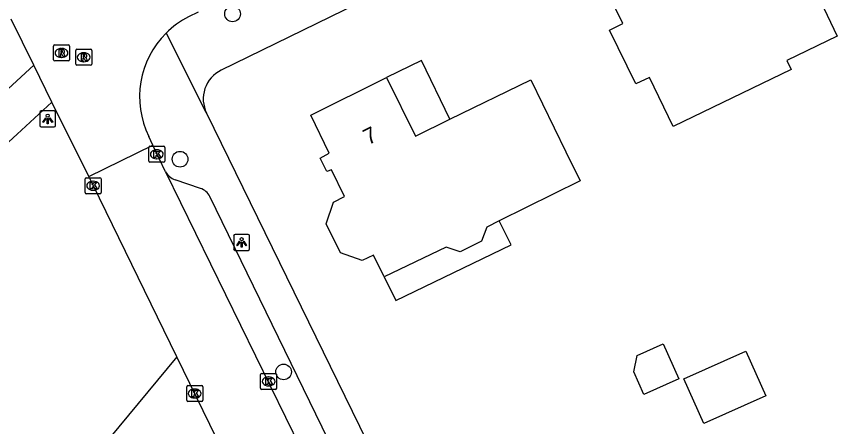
# Model space of a CAD drawing. Extents: x 160457 to 162082, y 388340 to 389736.
# Drawn here: x 160764.7 to 160816.2, y 388623.8 to 388649.4 of the extents above; entities that cross this region are included whole.
import ezdxf

# ---------------------------------------------------------------- set-up
doc = ezdxf.new("R2010")
doc.units = 0
for name, color, linetype in [('IMGEO_Boom', 7, 'Continuous'), ('IMGEO_Groenvoorziening', 7, 'Continuous'), ('IMGEO_Kolk', 7, 'Continuous'), ('IMGEO_Lichtpunt', 7, 'Continuous'), ('IMGEO_Pand', 7, 'Continuous'), ('IMGEO_Pand_nummerreeks', 7, 'Continuous'), ('IMGEO_Pand_overbouw', 7, 'Continuous'), ('IMGEO_Rijbaan_lokaal_open', 7, 'Continuous'), ('IMGEO_Rioolput', 7, 'Continuous'), ('IMGEO_Voetpad_open', 7, 'Continuous')]:
    doc.layers.add(name, color=color, linetype=linetype)

msp = doc.modelspace()

# ---------------------------------------------------------------- linework, layer by layer
at = {"layer": 'IMGEO_Boom'}
for centre in [(160778.162, 388649.577), (160774.883, 388640.505), (160781.349, 388627.22)]:
    msp.add_circle(centre, 0.489, dxfattribs=at)
at = {"layer": 'IMGEO_Groenvoorziening'}
msp.add_lwpolyline([(160774.68, 388628.159), (160767.455, 388619.42)], dxfattribs=at)
at = {"layer": 'IMGEO_Kolk'}
for p, q in [((160773.007, 388641.312), (160773.859, 388641.312)), ((160772.932, 388640.386), (160772.932, 388641.238)), ((160773.42, 388641.092), (160773.445, 388641.092)), ((160773.933, 388641.238), (160773.933, 388640.386)), ((160773.859, 388640.312), (160773.007, 388640.312)), ((160773.443, 388640.532), (160773.418, 388640.532)), ((160768.958, 388638.419), (160768.958, 388639.271)), ((160769.033, 388639.345), (160769.885, 388639.345)), ((160769.959, 388639.271), (160769.959, 388638.419)), ((160769.446, 388639.125), (160769.471, 388639.125)), ((160769.885, 388638.345), (160769.033, 388638.345)), ((160769.469, 388638.565), (160769.444, 388638.565)), ((160779.914, 388626.201), (160779.914, 388627.053)), ((160779.989, 388627.127), (160780.841, 388627.127)), ((160780.402, 388626.907), (160780.427, 388626.907)), ((160780.915, 388627.053), (160780.915, 388626.201)), ((160775.375, 388626.371), (160776.227, 388626.371)), ((160780.425, 388626.347), (160780.4, 388626.347)), ((160775.3, 388625.445), (160775.3, 388626.297)), ((160775.788, 388626.151), (160775.813, 388626.151)), ((160776.301, 388626.297), (160776.301, 388625.445)), ((160780.841, 388626.127), (160779.989, 388626.127)), ((160776.227, 388625.371), (160775.375, 388625.371)), ((160775.811, 388625.591), (160775.786, 388625.591))]:
    msp.add_line(p, q, dxfattribs=at)
for points in [[(160773.007, 388641.312), (160773.859, 388641.312)], [(160772.932, 388640.386), (160772.932, 388641.238)], [(160773.253, 388641.012), (160773.376, 388641.012), (160773.376, 388640.861), (160773.506, 388641.012), (160773.67, 388641.012), (160773.524, 388640.861), (160773.677, 388640.612), (160773.525, 388640.612), (160773.44, 388640.776), (160773.376, 388640.709), (160773.376, 388640.612), (160773.253, 388640.612), (160773.253, 388641.012)], [(160773.933, 388641.238), (160773.933, 388640.386)], [(160773.859, 388640.312), (160773.007, 388640.312)], [(160768.958, 388638.419), (160768.958, 388639.271)], [(160769.033, 388639.345), (160769.885, 388639.345)], [(160769.959, 388639.271), (160769.959, 388638.419)], [(160769.279, 388639.045), (160769.402, 388639.045), (160769.402, 388638.894), (160769.532, 388639.045), (160769.696, 388639.045), (160769.55, 388638.894), (160769.703, 388638.645), (160769.551, 388638.645), (160769.466, 388638.809), (160769.402, 388638.742), (160769.402, 388638.645), (160769.279, 388638.645), (160769.279, 388639.045)], [(160769.885, 388638.345), (160769.033, 388638.345)], [(160779.914, 388626.201), (160779.914, 388627.053)], [(160779.989, 388627.127), (160780.841, 388627.127)], [(160780.235, 388626.827), (160780.358, 388626.827), (160780.358, 388626.676), (160780.488, 388626.827), (160780.652, 388626.827), (160780.506, 388626.676), (160780.659, 388626.427), (160780.507, 388626.427), (160780.422, 388626.591), (160780.358, 388626.524), (160780.358, 388626.427), (160780.235, 388626.427), (160780.235, 388626.827)], [(160780.915, 388627.053), (160780.915, 388626.201)], [(160775.375, 388626.371), (160776.227, 388626.371)], [(160775.3, 388625.445), (160775.3, 388626.297)], [(160775.621, 388626.071), (160775.744, 388626.071), (160775.744, 388625.92), (160775.874, 388626.071), (160776.038, 388626.071), (160775.892, 388625.92), (160776.045, 388625.671), (160775.893, 388625.671), (160775.808, 388625.835), (160775.744, 388625.768), (160775.744, 388625.671), (160775.621, 388625.671), (160775.621, 388626.071)], [(160776.301, 388626.297), (160776.301, 388625.445)], [(160780.841, 388626.127), (160779.989, 388626.127)], [(160776.227, 388625.371), (160775.375, 388625.371)]]:
    msp.add_lwpolyline(points, dxfattribs=at)
for centre, start, end in [((160773.009, 388641.236), 91.552, 178.448), ((160773.009, 388641.236), 91.552, 178.448), ((160773.857, 388641.236), 1.552, 88.448), ((160773.857, 388641.236), 1.552, 88.448), ((160773.009, 388640.388), 181.552, 268.448), ((160773.009, 388640.388), 181.552, 268.448), ((160773.857, 388640.388), 271.552, 358.448), ((160773.857, 388640.388), 271.552, 358.448), ((160769.035, 388639.269), 91.552, 178.448), ((160769.035, 388639.269), 91.552, 178.448), ((160769.883, 388639.269), 1.552, 88.448), ((160769.883, 388639.269), 1.552, 88.448), ((160769.035, 388638.421), 181.552, 268.448), ((160769.035, 388638.421), 181.552, 268.448), ((160769.883, 388638.421), 271.552, 358.448), ((160769.883, 388638.421), 271.552, 358.448), ((160779.991, 388627.051), 91.552, 178.448), ((160779.991, 388627.051), 91.552, 178.448), ((160780.839, 388627.051), 1.552, 88.448), ((160780.839, 388627.051), 1.552, 88.448), ((160775.377, 388626.295), 91.552, 178.448), ((160775.377, 388626.295), 91.552, 178.448), ((160776.225, 388626.295), 1.552, 88.448), ((160776.225, 388626.295), 1.552, 88.448), ((160779.991, 388626.203), 181.552, 268.448), ((160779.991, 388626.203), 181.552, 268.448), ((160780.839, 388626.203), 271.552, 358.448), ((160780.839, 388626.203), 271.552, 358.448), ((160775.377, 388625.447), 181.552, 268.448), ((160775.377, 388625.447), 181.552, 268.448), ((160776.225, 388625.447), 271.552, 358.448), ((160776.225, 388625.447), 271.552, 358.448)]:
    msp.add_arc(centre, 0.0765, start, end, dxfattribs=at)
for centre, major_axis, ratio, start_param, end_param in [((160773.419, 388640.812), (-0.387, 0.002), 0.722429, 4.712389, 7.853982), ((160773.444, 388640.812), (-0.39, 0.002), 0.717154, 1.570796, 4.712389), ((160769.445, 388638.845), (-0.387, 0.002), 0.722429, 4.712389, 7.853982), ((160769.47, 388638.845), (-0.39, 0.002), 0.717154, 1.570796, 4.712389), ((160780.401, 388626.627), (-0.387, 0.002), 0.722429, 4.712389, 7.853982), ((160780.426, 388626.627), (-0.39, 0.002), 0.717154, 1.570796, 4.712389), ((160775.787, 388625.871), (-0.387, 0.002), 0.722429, 4.712389, 7.853982), ((160775.812, 388625.871), (-0.39, 0.002), 0.717154, 1.570796, 4.712389)]:
    msp.add_ellipse(centre, major_axis=major_axis, ratio=ratio, start_param=start_param, end_param=end_param, dxfattribs=at)
at = {"layer": 'IMGEO_Lichtpunt'}
for p, q in [((160766.125, 388643.422), (160766.125, 388642.615)), ((160766.125, 388643.422), (160766.125, 388642.615)), ((160767.027, 388643.517), (160766.219, 388643.517)), ((160767.027, 388643.517), (160766.219, 388643.517)), ((160767.121, 388642.615), (160767.121, 388643.422)), ((160767.121, 388642.615), (160767.121, 388643.422)), ((160766.219, 388642.521), (160767.027, 388642.521)), ((160766.219, 388642.521), (160767.027, 388642.521)), ((160778.232, 388635.713), (160778.232, 388634.906)), ((160778.232, 388635.713), (160778.232, 388634.906)), ((160779.134, 388635.808), (160778.326, 388635.808)), ((160779.134, 388635.808), (160778.326, 388635.808)), ((160779.228, 388634.906), (160779.228, 388635.713)), ((160779.228, 388634.906), (160779.228, 388635.713)), ((160778.326, 388634.812), (160779.134, 388634.812)), ((160778.326, 388634.812), (160779.134, 388634.812))]:
    msp.add_line(p, q, dxfattribs=at)
for points in [[(160766.499, 388643.086), (160766.538, 388643.058), (160766.35, 388642.796), (160766.312, 388642.823), (160766.499, 388643.086)], [(160766.601, 388643.038), (160766.648, 388643.038), (160766.648, 388642.716), (160766.601, 388642.716), (160766.601, 388643.038)], [(160766.711, 388643.058), (160766.749, 388643.085), (160766.936, 388642.823), (160766.897, 388642.795), (160766.711, 388643.058)], [(160778.606, 388635.377), (160778.645, 388635.349), (160778.457, 388635.087), (160778.419, 388635.114), (160778.606, 388635.377)], [(160778.708, 388635.329), (160778.755, 388635.329), (160778.755, 388635.007), (160778.708, 388635.007), (160778.708, 388635.329)], [(160778.818, 388635.349), (160778.856, 388635.376), (160779.043, 388635.114), (160779.004, 388635.086), (160778.818, 388635.349)]]:
    msp.add_lwpolyline(points, dxfattribs=at)
for centre in [(160766.624, 388643.22), (160778.731, 388635.511)]:
    msp.add_circle(centre, 0.0994, dxfattribs=at)
for centre, start, end in [((160766.219, 388643.422), 90, 180), ((160766.219, 388643.422), 90, 180), ((160767.027, 388643.422), 0, 90), ((160767.027, 388643.422), 0, 90), ((160766.219, 388642.615), 180, 270), ((160766.219, 388642.615), 180, 270), ((160767.027, 388642.615), 270, 0), ((160767.027, 388642.615), 270, 360), ((160778.326, 388635.713), 90, 180), ((160778.326, 388635.713), 90, 180), ((160779.134, 388635.713), 0, 90), ((160779.134, 388635.713), 0, 90), ((160778.326, 388634.906), 180, 270), ((160778.326, 388634.906), 180, 270), ((160779.134, 388634.906), 270, 0), ((160779.134, 388634.906), 270, 360)]:
    msp.add_arc(centre, 0.0946, start, end, dxfattribs=at)
at = {"layer": 'IMGEO_Pand'}
for points in [[(160803.322, 388645.208), (160801.68, 388648.558), (160802.525, 388648.971), (160801.014, 388652.061), (160808.386, 388655.648), (160809.939, 388652.456), (160813.089, 388653.988), (160815.272, 388649.49), (160815.901, 388648.194), (160812.757, 388646.669), (160813.028, 388646.113), (160805.662, 388642.539), (160804.175, 388645.61), (160803.322, 388645.208)], [(160787.615, 388633.148), (160786.95, 388634.517), (160786.249, 388634.188), (160784.909, 388634.649), (160784.005, 388636.474), (160784.453, 388637.827), (160785.156, 388638.175), (160784.348, 388639.831), (160784.042, 388639.726), (160783.63, 388640.568), (160784.199, 388640.874), (160783.058, 388643.254), (160787.772, 388645.597), (160789.57, 388641.947), (160791.725, 388642.998), (160796.771, 388645.458), (160798.965, 388640.966), (160799.852, 388639.15), (160794.809, 388636.654), (160794.022, 388636.26), (160793.707, 388635.386), (160792.363, 388634.724), (160791.488, 388635.019), (160787.615, 388633.148)], [(160803.841, 388625.817), (160803.21, 388627.225), (160803.414, 388628.236), (160805.038, 388628.964), (160806.012, 388626.79), (160803.841, 388625.817)], [(160807.583, 388623.992), (160806.33, 388626.789), (160810.19, 388628.514), (160811.443, 388625.718), (160807.583, 388623.992)]]:
    msp.add_lwpolyline(points, dxfattribs=at)
at = {"layer": 'IMGEO_Pand_overbouw'}
for points in [[(160787.772, 388645.597), (160789.57, 388641.947), (160791.725, 388642.998), (160789.952, 388646.666)], [(160794.809, 388636.654), (160794.022, 388636.26), (160793.707, 388635.386), (160792.363, 388634.724), (160791.488, 388635.019), (160787.615, 388633.148), (160788.343, 388631.688), (160795.545, 388635.162)]]:
    msp.add_lwpolyline(points, close=True, dxfattribs=at)
at = {"layer": 'IMGEO_Rijbaan_lokaal_open'}
for points in [[(160776.016, 388649.694), (160775.409, 388649.391)], [(160765.757, 388646.373), (160764.339, 388649.243)], [(160766.892, 388644.075), (160765.757, 388646.373)], [(160769.189, 388639.422), (160766.892, 388644.075)], [(160773.193, 388641.371), (160772.927, 388641.931)], [(160769.189, 388639.422), (160773.193, 388641.371)], [(160773.981, 388639.715), (160773.193, 388641.371)], [(160773.981, 388639.715), (160786.14, 388614.827), (160786.963, 388613.109)], [(160774.68, 388628.159), (160769.46, 388638.873), (160769.189, 388639.422)], [(160782.482, 388612.146), (160774.68, 388628.159)]]:
    msp.add_lwpolyline(points, dxfattribs=at)
for centre, radius, start, end in [((160777.959, 388644.416), 5.59, 117.1395, 134.886), ((160777.974, 388644.395), 5.616, 134.84, 206.0164)]:
    msp.add_arc(centre, radius, start, end, dxfattribs=at)
at = {"layer": 'IMGEO_Rioolput'}
for p, q in [((160766.986, 388646.713), (160766.986, 388647.565)), ((160767.061, 388647.639), (160767.913, 388647.639)), ((160767.987, 388647.565), (160767.987, 388646.713)), ((160767.474, 388647.419), (160767.499, 388647.419)), ((160768.374, 388646.444), (160768.374, 388647.296)), ((160768.449, 388647.37), (160769.301, 388647.37)), ((160768.862, 388647.15), (160768.887, 388647.15)), ((160769.375, 388647.296), (160769.375, 388646.444)), ((160767.913, 388646.639), (160767.061, 388646.639)), ((160767.497, 388646.859), (160767.472, 388646.859)), ((160768.885, 388646.59), (160768.86, 388646.59)), ((160769.301, 388646.37), (160768.449, 388646.37))]:
    msp.add_line(p, q, dxfattribs=at)
for points in [[(160766.986, 388646.713), (160766.986, 388647.565)], [(160767.061, 388647.639), (160767.913, 388647.639)], [(160767.987, 388647.565), (160767.987, 388646.713)], [(160767.575, 388647.337), (160767.323, 388647.339), (160767.323, 388646.939)], [(160767.323, 388646.939), (160767.447, 388646.939), (160767.447, 388647.101), (160767.458, 388647.101)], [(160767.501, 388647.258), (160767.447, 388647.258), (160767.447, 388647.177)], [(160767.447, 388647.177), (160767.499, 388647.177)], [(160767.505, 388647.072), (160767.576, 388646.939), (160767.716, 388646.939), (160767.651, 388647.065)], [(160768.374, 388646.444), (160768.374, 388647.296)], [(160768.449, 388647.37), (160769.301, 388647.37)], [(160768.963, 388647.068), (160768.711, 388647.07), (160768.711, 388646.67)], [(160768.889, 388646.989), (160768.835, 388646.989), (160768.835, 388646.908)], [(160769.375, 388647.296), (160769.375, 388646.444)], [(160767.913, 388646.639), (160767.061, 388646.639)], [(160768.711, 388646.67), (160768.835, 388646.67), (160768.835, 388646.832), (160768.846, 388646.832)], [(160768.835, 388646.908), (160768.887, 388646.908)], [(160768.893, 388646.803), (160768.964, 388646.67), (160769.104, 388646.67), (160769.039, 388646.796)], [(160769.301, 388646.37), (160768.449, 388646.37)]]:
    msp.add_lwpolyline(points, dxfattribs=at)
for centre, radius, start, end in [((160767.063, 388647.563), 0.0765, 91.552, 178.448), ((160767.063, 388647.563), 0.0765, 91.552, 178.448), ((160767.911, 388647.563), 0.0765, 1.552, 88.448), ((160767.911, 388647.563), 0.0765, 1.552, 88.448), ((160767.457, 388647.048), 0.0533, 26.0293, 88.6989), ((160767.483, 388647.366), 0.19, 274.7715, 282.9687), ((160767.507, 388647.162), 0.0964, 77.0061, 93.1865), ((160767.521, 388647.219), 0.0378, 276.6634, 79.6772), ((160767.574, 388647.227), 0.109, 350.3612, 89.416), ((160767.572, 388647.227), 0.112, 277.5842, 350.9817), ((160767.556, 388647.012), 0.108, 29.5134, 73.7905), ((160768.451, 388647.294), 0.0765, 91.552, 178.448), ((160768.451, 388647.294), 0.0765, 91.552, 178.448), ((160768.895, 388646.893), 0.0964, 77.0061, 93.1865), ((160768.909, 388646.95), 0.0378, 276.6634, 79.6772), ((160768.962, 388646.958), 0.109, 350.3612, 89.416), ((160768.96, 388646.958), 0.112, 277.5842, 350.9817), ((160769.299, 388647.294), 0.0765, 1.552, 88.448), ((160769.299, 388647.294), 0.0765, 1.552, 88.448), ((160767.063, 388646.715), 0.0765, 181.552, 268.448), ((160767.063, 388646.715), 0.0765, 181.552, 268.448), ((160767.911, 388646.715), 0.0765, 271.552, 358.448), ((160767.911, 388646.715), 0.0765, 271.552, 358.448), ((160768.451, 388646.446), 0.0765, 181.552, 268.448), ((160768.451, 388646.446), 0.0765, 181.552, 268.448), ((160768.845, 388646.779), 0.0533, 26.0293, 88.6989), ((160768.871, 388647.097), 0.19, 274.7715, 282.9687), ((160768.944, 388646.743), 0.108, 29.5134, 73.7905), ((160769.299, 388646.446), 0.0765, 271.552, 358.448), ((160769.299, 388646.446), 0.0765, 271.552, 358.448)]:
    msp.add_arc(centre, radius, start, end, dxfattribs=at)
for centre, major_axis, ratio, start_param, end_param in [((160767.473, 388647.139), (-0.387, 0.002), 0.722429, 4.712389, 7.853982), ((160767.498, 388647.139), (-0.39, 0.002), 0.717154, 1.570796, 4.712389), ((160768.861, 388646.87), (-0.387, 0.002), 0.722429, 4.712389, 7.853982), ((160768.886, 388646.87), (-0.39, 0.002), 0.717154, 1.570796, 4.712389)]:
    msp.add_ellipse(centre, major_axis=major_axis, ratio=ratio, start_param=start_param, end_param=end_param, dxfattribs=at)
at = {"layer": 'IMGEO_Voetpad_open'}
for points in [[(160828.347, 388670.932), (160777.455, 388646.059)], [(160774.014, 388648.377), (160776.502, 388643.452), (160776.541, 388643.382)], [(160745.684, 388627.869), (160765.757, 388646.373)], [(160741.437, 388620.594), (160766.892, 388644.075)], [(160776.541, 388643.382), (160788.81, 388618.259)], [(160776.152, 388638.68), (160774.572, 388639.218)], [(160788.436, 388614.156), (160776.749, 388638.166)]]:
    msp.add_lwpolyline(points, dxfattribs=at)
for centre, radius, start, end in [((160778.327, 388644.267), 1.993, 115.9534, 206.344), ((160774.958, 388640.277), 1.127, 209.9096, 249.9663), ((160775.865, 388637.743), 0.98, 25.5718, 72.9732)]:
    msp.add_arc(centre, radius, start, end, dxfattribs=at)

# ---------------------------------------------------------------- texts
at = {"layer": 'IMGEO_Pand_nummerreeks'}
msp.add_text('7', height=1, rotation=26.4288, dxfattribs=at).set_placement((160786.628, 388641.366))

doc.saveas('drawing.dxf')
